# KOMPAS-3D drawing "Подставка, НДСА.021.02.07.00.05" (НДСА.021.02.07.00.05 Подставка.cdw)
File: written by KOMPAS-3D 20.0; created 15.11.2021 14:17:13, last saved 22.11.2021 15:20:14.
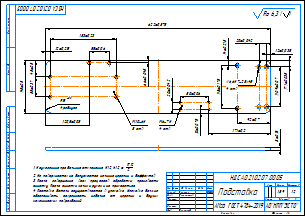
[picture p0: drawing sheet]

Sheet 1: A3, landscape

Document properties: Знак неуказанной шероховатости: 4; Параметр неуказанной шероховатости: Ra 6,3; 288671597874: <item xmlns="http://appius.ru/pdm" xmlns:xs="http://www.w3.org/2001/XMLSchema" xmlns:xsi="http://www.w3.org/2001/XMLSchema-instance" xsi:type="item">  <element xmlns:d2p1="http://v8.1c.ru/8.1/data/enterprise/current-config" xsi:type="d2p1:CatalogRef.aps_Элемен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; 288671598074: <item xmlns="http://appius.ru/pdm" xmlns:xs="http://www.w3.org/2001/XMLSchema" xmlns:xsi="http://www.w3.org/2001/XMLSchema-instance" xsi:type="item">  <element xmlns:d2p1="http://v8.1c.ru/8.1/data/enterprise/current-config" xsi:type="d2p1:CatalogRef.aps_Элемен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; 236883207385: <item xmlns="http://appius.ru/pdm" xmlns:xs="http://www.w3.org/2001/XMLSchema" xmlns:xsi="http://www.w3.org/2001/XMLSchema-instance" xsi:type="item">  <element xmlns:d2p1="http://v8.1c.ru/8.1/data/enterprise/current-config" xsi:type="d2p1:CatalogRef.aps_Элемен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; 236883207485: <item xmlns="http://appius.ru/pdm" xmlns:xs="http://www.w3.org/2001/XMLSchema" xmlns:xsi="http://www.w3.org/2001/XMLSchema-instance" xsi:type="item">  <element xmlns:d2p1="http://v8.1c.ru/8.1/data/enterprise/current-config" xsi:type="d2p1:CatalogRef.aps_Элемен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; 337069468745: <item xmlns="http://appius.ru/pdm" xmlns:xs="http://www.w3.org/2001/XMLSchema" xmlns:xsi="http://www.w3.org/2001/XMLSchema-instance" xsi:type="item">  <element xmlns:d2p1="http://v8.1c.ru/8.1/data/enterprise/current-config" xsi:type="d2p1:CatalogRef.aps_Элемен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; 337069468945: <item xmlns="http://appius.ru/pdm" xmlns:xs="http://www.w3.org/2001/XMLSchema" xmlns:xsi="http://www.w3.org/2001/XMLSchema-instance" xsi:type="item">  <element xmlns:d2p1="http://v8.1c.ru/8.1/data/enterprise/current-config" xsi:type="d2p1:CatalogRef.aps_Элемен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; PLM_CDWXDTO: <item xmlns="http://appius.ru/pdm" xmlns:xs="http://www.w3.org/2001/XMLSchema" xmlns:xsi="http://www.w3.org/2001/XMLSchema-instance" xsi:type="item">  <element xmlns:d2p1="http://v8.1c.ru/8.1/data/enterprise/current-config" xsi:type="d2p1:CatalogRef.aps_Элемен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; Масса: 1.88583; PDM_DOCXDTO: <item xmlns="http://appius.ru/pdm" xmlns:xs="http://www.w3.org/2001/XMLSchema" xmlns:xsi="http://www.w3.org/2001/XMLSchema-instance" xsi:type="item">  <element xmlns:d2p1="http://v8.1c.ru/8.1/data/enterprise/current-config" xsi:type="d2p1:CatalogRef.aps_Элемен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; PDM_ITEMXDTO: <item xmlns="http://appius.ru/pdm" xmlns:xs="http://www.w3.org/2001/XMLSchema" xmlns:xsi="http://www.w3.org/2001/XMLSchema-instance" xsi:type="item">  <element xmlns:d2p1="http://v8.1c.ru/8.1/data/enterprise/current-config" xsi:type="d2p1:CatalogRef.aps_Элемен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; PDM_DRAWINGXDTO: <item xmlns="http://appius.ru/pdm" xmlns:xs="http://www.w3.org/2001/XMLSchema" xmlns:xsi="http://www.w3.org/2001/XMLSchema-instance" xsi:type="item">  <element xmlns:d2p1="http://v8.1c.ru/8.1/data/enterprise/current-config" xsi:type="d2p1:CatalogRef.aps_Элемен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

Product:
- Part/product: Подставка  | designation НДСА.021.02.07.00.05
    Материал: АМг6  ГОСТ 4784-2019 (density 2640 kg/m3)
    Масса: 1.88583
    additional columns: <item xmlns="http://appius.ru/pdm" xmlns:xs="http://www.w3.org/2001/XMLSchema" x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; <item xmlns="http://appius.ru/pdm" xmlns:xs="http://www.w3.org/2001/XMLSchema" x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; <item xmlns="http://appius.ru/pdm" xmlns:xs="http://www.w3.org/2001/XMLSchema" x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; <item xmlns="http://appius.ru/pdm" xmlns:xs="http://www.w3.org/2001/XMLSchema" x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; <item xmlns="http://appius.ru/pdm" xmlns:xs="http://www.w3.org/2001/XMLSchema" x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; <item xmlns="http://appius.ru/pdm" xmlns:xs="http://www.w3.org/2001/XMLSchema" x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; <item xmlns="http://appius.ru/pdm" xmlns:xs="http://www.w3.org/2001/XMLSchema" x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; <item xmlns="http://appius.ru/pdm" xmlns:xs="http://www.w3.org/2001/XMLSchema" x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
    source file: НДСА.021.02.07.00.05 Подставка.cdw

Title block, sheet 1: Наименование: Подставка; designation: НДСА.021.02.07.00.05; Материал: АМг6  ГОСТ 4784-2019; Масса: 1,89; Количество листов документа: 1; organisation: АО"НПП"ЭСТО"; Форматы листов документа: A3; stored path: C:\Users\korychko\Desktop\PLM\НДСА.021.02.07.00.05 Подставка.cdw; Разработал: Корячко; Проверил: Горностаев; Утвердил: Белецкий; Разработал, date: 15.11.2021

Views: Вид 1, Сверху, Проекционный вид 2
Referenced files in C:\Users\korychko\Desktop\PLM\: НДСА.021.02.07.00.05 Подставка.m3d
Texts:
  JS15
  JS12
  JS11
  JS10
  Ra 6,3
  Ra 6,3 ( )
  НДСА.021.02.07.00.05 Подставка
Dimensions and other numbers on the sheet: 145±0,5; 622±0,875; 15; 4 радиуса; 45±0,5; 55±0,37; 12±0,215; 183±0,23; 6,6±0,045; 120,5±0,08; 14±0,215; 118±0,175; 92±0,7; 20±0,042; 110,9±0,07; 17,1±0,035; -6H; 10±0,075; 8 отв.; 4 отв.; 80±0,06; 171±0,2; -7H; 6; 8±0,18; 1:2; 1; 1,89; 15.11.2021

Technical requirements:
  Неуказанные предельные отклонения H12, h12,    IT12 2 .
  На поверхностях не допускается наличие царапин и деффектов.
  После завершения всех процессов обработки произвести
  очистку. После очистки голыми руками не прикосаться.
  Поставка детали осуществляется в упаковке. Упаковка должна
  обеспечивать сохранность изделия от царапин и других
  механических повреждений.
